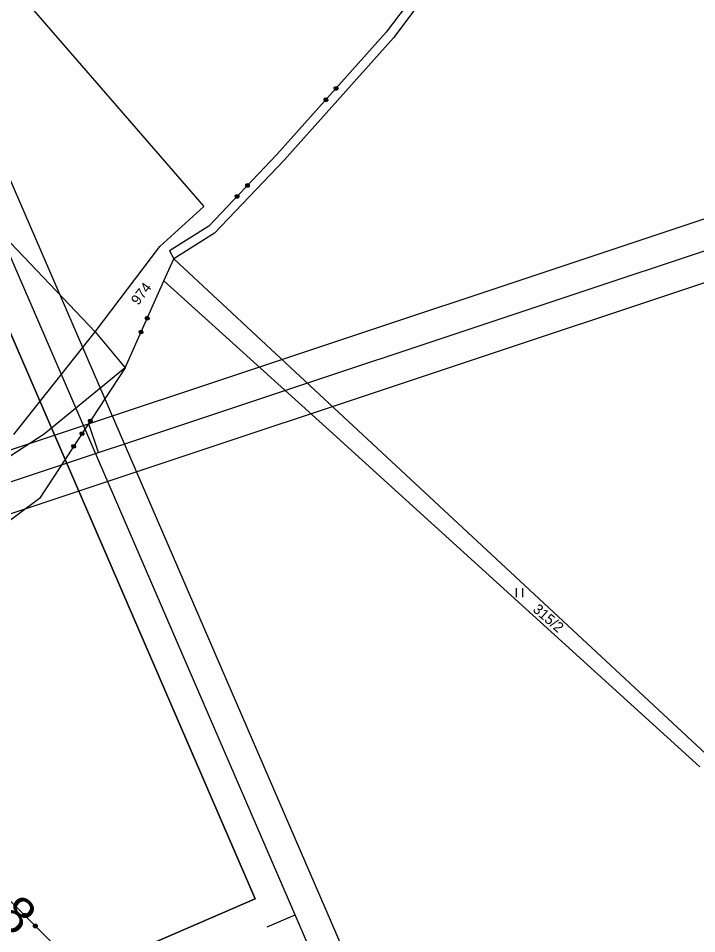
# Model space of a CAD drawing. Extents: x -866656 to -858817, y -1041816 to -1038653.
# Drawn here: x -864585 to -864473.3, y -1041373 to -1041222.2 of the extents above; entities that cross this region are included whole.
import ezdxf

# ---------------------------------------------------------------- set-up
doc = ezdxf.new("R2010")
doc.units = 0
for name, color, linetype in [('tisk ramy', 7, 'Continuous'), ('Vrstva 1', 7, 'Continuous'), ('Vrstva 3', 7, 'Continuous'), ('Vrstva 7', 7, 'Continuous')]:
    doc.layers.add(name, color=color, linetype=linetype)

msp = doc.modelspace()

# ---------------------------------------------------------------- linework, layer by layer
at = {"layer": 'tisk ramy'}
for p, q in [((-864571.85, -1041293.7), (-864573.43, -1041288.96)), ((-864544.02, -1041371.84), (-864539.44, -1041369.86))]:
    msp.add_line(p, q, dxfattribs=at)
for points in [[(-865224.28, -1040522.07), (-864724.07, -1041678.52), (-864451.49, -1041560.62), (-864951.69, -1040404.17)], [(-864954.3, -1040410.74), (-864458.06, -1041558.01), (-864721.47, -1041671.94), (-865217.7, -1040524.67)], [(-865211.14, -1040527.28), (-864800.25, -1041477.22), (-864546.01, -1041367.26), (-864956.9, -1040417.31)], [(-864956.9, -1040417.31), (-864546.01, -1041367.26), (-864800.25, -1041477.22), (-865211.14, -1040527.28)], [(-864678.84, -1041637.08), (-863881.88, -1041371.71), (-863975.7, -1041089.93), (-864772.67, -1041355.3)], [(-863888.2, -1041368.54), (-864675.68, -1041630.76), (-864766.35, -1041358.47), (-863978.87, -1041096.25)], [(-864672.52, -1041624.44), (-864089.02, -1041430.15), (-864176.53, -1041167.33), (-864760.03, -1041361.63)]]:
    msp.add_lwpolyline(points, close=True, dxfattribs=at)
at = {"layer": 'Vrstva 1'}
for p, q in [((-864624.71, -1041172.2), (-864554.46, -1041253.14)), ((-864513.59, -1041212.5), (-864523.24, -1041225.36)), ((-864523.24, -1041225.36), (-864541.25, -1041245.54)), ((-864541.25, -1041245.54), (-864552.72, -1041257.58)), ((-864561.73, -1041259.78), (-864554.46, -1041253.14)), ((-864552.72, -1041257.58), (-864559.43, -1041261.8)), ((-864572.38, -1041273.79), (-864561.73, -1041259.78)), ((-864530.65, -1041288.58), (-864559.43, -1041261.8)), ((-864561.06, -1041265.43), (-864533.75, -1041290.09)), ((-864585.8, -1041290.74), (-864572.38, -1041273.79)), ((-864567.45, -1041279.73), (-864580.81, -1041290.66)), ((-864470.92, -1041344.11), (-864530.65, -1041288.58)), ((-864580.81, -1041290.66), (-864609.48, -1041309.4)), ((-864533.75, -1041290.09), (-864472.75, -1041345.47)), ((-864502.98, -1041317.55), (-864502.98, -1041316.05)), ((-864501.98, -1041316.05), (-864501.98, -1041317.55))]:
    msp.add_line(p, q, dxfattribs=at)
at = {"layer": 'Vrstva 3'}
for p, q in [((-864514.79, -1041211.61), (-864524.44, -1041224.46)), ((-864524.44, -1041224.46), (-864542.42, -1041244.6)), ((-864524.44, -1041224.46), (-864542.42, -1041244.6)), ((-864532.99, -1041233.58), (-864532.85, -1041233.44)), ((-864532.99, -1041233.58), (-864532.85, -1041233.44)), ((-864532.97, -1041233.87), (-864532.99, -1041233.58)), ((-864532.97, -1041233.87), (-864532.99, -1041233.58)), ((-864532.82, -1041234), (-864532.97, -1041233.87)), ((-864532.82, -1041234), (-864532.97, -1041233.87)), ((-864532.91, -1041233.65), (-864532.78, -1041233.5)), ((-864532.91, -1041233.65), (-864532.78, -1041233.5)), ((-864532.61, -1041233.92), (-864532.91, -1041233.65)), ((-864532.61, -1041233.92), (-864532.91, -1041233.65)), ((-864532.91, -1041233.79), (-864532.76, -1041233.93)), ((-864532.91, -1041233.79), (-864532.76, -1041233.93)), ((-864532.85, -1041233.44), (-864532.57, -1041233.42)), ((-864532.85, -1041233.44), (-864532.57, -1041233.42)), ((-864532.85, -1041233.58), (-864532.55, -1041233.84)), ((-864532.85, -1041233.58), (-864532.55, -1041233.84)), ((-864532.54, -1041233.98), (-864532.82, -1041234)), ((-864532.54, -1041233.98), (-864532.82, -1041234)), ((-864532.78, -1041233.5), (-864532.48, -1041233.77)), ((-864532.78, -1041233.5), (-864532.48, -1041233.77)), ((-864532.76, -1041233.93), (-864532.61, -1041233.92)), ((-864532.76, -1041233.93), (-864532.61, -1041233.92)), ((-864532.49, -1041233.63), (-864532.64, -1041233.49)), ((-864532.49, -1041233.63), (-864532.64, -1041233.49)), ((-864532.57, -1041233.42), (-864532.42, -1041233.55)), ((-864532.57, -1041233.42), (-864532.42, -1041233.55)), ((-864532.41, -1041233.83), (-864532.54, -1041233.98)), ((-864532.41, -1041233.83), (-864532.54, -1041233.98)), ((-864532.48, -1041233.77), (-864532.49, -1041233.63)), ((-864532.48, -1041233.77), (-864532.49, -1041233.63)), ((-864532.42, -1041233.55), (-864532.41, -1041233.83)), ((-864532.42, -1041233.55), (-864532.41, -1041233.83)), ((-864534.65, -1041235.45), (-864534.52, -1041235.3)), ((-864534.65, -1041235.45), (-864534.52, -1041235.3)), ((-864534.64, -1041235.73), (-864534.65, -1041235.45)), ((-864534.64, -1041235.73), (-864534.65, -1041235.45)), ((-864534.49, -1041235.86), (-864534.64, -1041235.73)), ((-864534.49, -1041235.86), (-864534.64, -1041235.73)), ((-864534.58, -1041235.52), (-864534.44, -1041235.37)), ((-864534.58, -1041235.52), (-864534.44, -1041235.37)), ((-864534.28, -1041235.78), (-864534.58, -1041235.52)), ((-864534.28, -1041235.78), (-864534.58, -1041235.52)), ((-864534.57, -1041235.66), (-864534.42, -1041235.79)), ((-864534.57, -1041235.66), (-864534.42, -1041235.79)), ((-864534.52, -1041235.3), (-864534.24, -1041235.28)), ((-864534.52, -1041235.3), (-864534.24, -1041235.28)), ((-864534.51, -1041235.44), (-864534.21, -1041235.71)), ((-864534.51, -1041235.44), (-864534.21, -1041235.71)), ((-864534.21, -1041235.85), (-864534.49, -1041235.86)), ((-864534.21, -1041235.85), (-864534.49, -1041235.86)), ((-864534.44, -1041235.37), (-864534.15, -1041235.63)), ((-864534.44, -1041235.37), (-864534.15, -1041235.63)), ((-864534.42, -1041235.79), (-864534.28, -1041235.78)), ((-864534.42, -1041235.79), (-864534.28, -1041235.78)), ((-864534.15, -1041235.49), (-864534.3, -1041235.36)), ((-864534.15, -1041235.49), (-864534.3, -1041235.36)), ((-864534.24, -1041235.28), (-864534.09, -1041235.42)), ((-864534.24, -1041235.28), (-864534.09, -1041235.42)), ((-864534.07, -1041235.7), (-864534.21, -1041235.85)), ((-864534.07, -1041235.7), (-864534.21, -1041235.85)), ((-864534.15, -1041235.63), (-864534.15, -1041235.49)), ((-864534.15, -1041235.63), (-864534.15, -1041235.49)), ((-864534.09, -1041235.42), (-864534.07, -1041235.7)), ((-864534.09, -1041235.42), (-864534.07, -1041235.7)), ((-864604.47, -1041240.2), (-864572.38, -1041273.79)), ((-864604.47, -1041240.2), (-864572.38, -1041273.79)), ((-864542.42, -1041244.6), (-864553.66, -1041256.41)), ((-864542.42, -1041244.6), (-864553.66, -1041256.41)), ((-864547.57, -1041249.57), (-864547.43, -1041249.43)), ((-864547.57, -1041249.57), (-864547.43, -1041249.43)), ((-864547.56, -1041249.86), (-864547.57, -1041249.57)), ((-864547.56, -1041249.86), (-864547.57, -1041249.57)), ((-864547.42, -1041249.99), (-864547.56, -1041249.86)), ((-864547.42, -1041249.99), (-864547.56, -1041249.86)), ((-864547.49, -1041249.64), (-864547.36, -1041249.5)), ((-864547.49, -1041249.64), (-864547.36, -1041249.5)), ((-864547.21, -1041249.92), (-864547.49, -1041249.64)), ((-864547.21, -1041249.92), (-864547.49, -1041249.64)), ((-864547.49, -1041249.78), (-864547.35, -1041249.92)), ((-864547.49, -1041249.78), (-864547.35, -1041249.92)), ((-864547.43, -1041249.43), (-864547.15, -1041249.42)), ((-864547.43, -1041249.43), (-864547.15, -1041249.42)), ((-864547.43, -1041249.57), (-864547.14, -1041249.85)), ((-864547.43, -1041249.57), (-864547.14, -1041249.85)), ((-864547.13, -1041249.99), (-864547.42, -1041249.99)), ((-864547.13, -1041249.99), (-864547.42, -1041249.99)), ((-864547.36, -1041249.5), (-864547.07, -1041249.77)), ((-864547.36, -1041249.5), (-864547.07, -1041249.77)), ((-864547.35, -1041249.92), (-864547.21, -1041249.92)), ((-864547.35, -1041249.92), (-864547.21, -1041249.92)), ((-864547.07, -1041249.63), (-864547.22, -1041249.49)), ((-864547.07, -1041249.63), (-864547.22, -1041249.49)), ((-864547.15, -1041249.42), (-864547, -1041249.56)), ((-864547.15, -1041249.42), (-864547, -1041249.56)), ((-864546.99, -1041249.84), (-864547.13, -1041249.99)), ((-864546.99, -1041249.84), (-864547.13, -1041249.99)), ((-864547.07, -1041249.77), (-864547.07, -1041249.63)), ((-864547.07, -1041249.77), (-864547.07, -1041249.63)), ((-864547, -1041249.56), (-864546.99, -1041249.84)), ((-864547, -1041249.56), (-864546.99, -1041249.84)), ((-864549.29, -1041251.38), (-864549.15, -1041251.24)), ((-864549.29, -1041251.38), (-864549.15, -1041251.24)), ((-864549.28, -1041251.67), (-864549.29, -1041251.38)), ((-864549.28, -1041251.67), (-864549.29, -1041251.38)), ((-864549.22, -1041251.45), (-864549.08, -1041251.31)), ((-864549.22, -1041251.45), (-864549.08, -1041251.31)), ((-864548.93, -1041251.73), (-864549.22, -1041251.45)), ((-864548.93, -1041251.73), (-864549.22, -1041251.45)), ((-864549.15, -1041251.24), (-864548.87, -1041251.23)), ((-864549.15, -1041251.24), (-864548.87, -1041251.23)), ((-864549.15, -1041251.38), (-864548.86, -1041251.66)), ((-864549.15, -1041251.38), (-864548.86, -1041251.66)), ((-864549.08, -1041251.31), (-864548.79, -1041251.58)), ((-864549.08, -1041251.31), (-864548.79, -1041251.58)), ((-864548.79, -1041251.44), (-864548.94, -1041251.31)), ((-864548.79, -1041251.44), (-864548.94, -1041251.31)), ((-864548.87, -1041251.23), (-864548.72, -1041251.37)), ((-864548.87, -1041251.23), (-864548.72, -1041251.37)), ((-864548.79, -1041251.58), (-864548.79, -1041251.44)), ((-864548.79, -1041251.58), (-864548.79, -1041251.44)), ((-864548.72, -1041251.37), (-864548.72, -1041251.65)), ((-864548.72, -1041251.37), (-864548.72, -1041251.65)), ((-864549.14, -1041251.81), (-864549.28, -1041251.67)), ((-864549.14, -1041251.81), (-864549.28, -1041251.67)), ((-864549.21, -1041251.59), (-864549.07, -1041251.73)), ((-864549.21, -1041251.59), (-864549.07, -1041251.73)), ((-864548.86, -1041251.8), (-864549.14, -1041251.81)), ((-864548.86, -1041251.8), (-864549.14, -1041251.81)), ((-864549.07, -1041251.73), (-864548.93, -1041251.73)), ((-864549.07, -1041251.73), (-864548.93, -1041251.73)), ((-864548.72, -1041251.65), (-864548.86, -1041251.8)), ((-864548.72, -1041251.65), (-864548.86, -1041251.8)), ((-864553.66, -1041256.41), (-864560.14, -1041260.47)), ((-864553.66, -1041256.41), (-864560.14, -1041260.47)), ((-864560.14, -1041260.47), (-864559.43, -1041261.8)), ((-864560.14, -1041260.47), (-864559.43, -1041261.8)), ((-864561.06, -1041265.43), (-864559.43, -1041261.8)), ((-864561.06, -1041265.43), (-864559.43, -1041261.8)), ((-864567.45, -1041279.73), (-864561.06, -1041265.43)), ((-864567.45, -1041279.73), (-864561.06, -1041265.43)), ((-864564.12, -1041271.54), (-864564.04, -1041271.36)), ((-864564.12, -1041271.54), (-864564.04, -1041271.36)), ((-864564.02, -1041271.81), (-864564.12, -1041271.54)), ((-864564.02, -1041271.81), (-864564.12, -1041271.54)), ((-864564.04, -1041271.36), (-864563.78, -1041271.26)), ((-864564.04, -1041271.36), (-864563.78, -1041271.26)), ((-864564.03, -1041271.59), (-864563.95, -1041271.4)), ((-864564.03, -1041271.59), (-864563.95, -1041271.4)), ((-864563.66, -1041271.75), (-864564.03, -1041271.59)), ((-864563.66, -1041271.75), (-864564.03, -1041271.59)), ((-864563.84, -1041271.89), (-864564.02, -1041271.81)), ((-864563.84, -1041271.89), (-864564.02, -1041271.81)), ((-864563.99, -1041271.49), (-864563.62, -1041271.66)), ((-864563.99, -1041271.49), (-864563.62, -1041271.66)), ((-864563.98, -1041271.72), (-864563.8, -1041271.8)), ((-864563.98, -1041271.72), (-864563.8, -1041271.8)), ((-864563.95, -1041271.4), (-864563.58, -1041271.57)), ((-864563.95, -1041271.4), (-864563.58, -1041271.57)), ((-864563.57, -1041271.79), (-864563.84, -1041271.89)), ((-864563.57, -1041271.79), (-864563.84, -1041271.89)), ((-864563.63, -1041271.43), (-864563.82, -1041271.35)), ((-864563.63, -1041271.43), (-864563.82, -1041271.35)), ((-864563.8, -1041271.8), (-864563.66, -1041271.75)), ((-864563.8, -1041271.8), (-864563.66, -1041271.75)), ((-864563.78, -1041271.26), (-864563.59, -1041271.34)), ((-864563.78, -1041271.26), (-864563.59, -1041271.34)), ((-864563.58, -1041271.57), (-864563.63, -1041271.43)), ((-864563.58, -1041271.57), (-864563.63, -1041271.43)), ((-864563.59, -1041271.34), (-864563.49, -1041271.61)), ((-864563.59, -1041271.34), (-864563.49, -1041271.61)), ((-864563.49, -1041271.61), (-864563.57, -1041271.79)), ((-864563.49, -1041271.61), (-864563.57, -1041271.79)), ((-864572.38, -1041273.79), (-864567.45, -1041279.73)), ((-864572.38, -1041273.79), (-864567.45, -1041279.73)), ((-864565.14, -1041273.83), (-864565.06, -1041273.64)), ((-864565.14, -1041273.83), (-864565.06, -1041273.64)), ((-864565.04, -1041274.09), (-864565.14, -1041273.83)), ((-864565.04, -1041274.09), (-864565.14, -1041273.83)), ((-864565.06, -1041273.64), (-864564.8, -1041273.54)), ((-864565.06, -1041273.64), (-864564.8, -1041273.54)), ((-864565.05, -1041273.87), (-864564.97, -1041273.69)), ((-864565.05, -1041273.87), (-864564.97, -1041273.69)), ((-864564.68, -1041274.03), (-864565.05, -1041273.87)), ((-864564.68, -1041274.03), (-864565.05, -1041273.87)), ((-864564.86, -1041274.17), (-864565.04, -1041274.09)), ((-864564.86, -1041274.17), (-864565.04, -1041274.09)), ((-864565.01, -1041273.78), (-864564.64, -1041273.94)), ((-864565.01, -1041273.78), (-864564.64, -1041273.94)), ((-864565, -1041274), (-864564.82, -1041274.08)), ((-864565, -1041274), (-864564.82, -1041274.08)), ((-864564.97, -1041273.69), (-864564.6, -1041273.85)), ((-864564.97, -1041273.69), (-864564.6, -1041273.85)), ((-864564.59, -1041274.07), (-864564.86, -1041274.17)), ((-864564.59, -1041274.07), (-864564.86, -1041274.17)), ((-864564.65, -1041273.72), (-864564.83, -1041273.63)), ((-864564.65, -1041273.72), (-864564.83, -1041273.63)), ((-864564.82, -1041274.08), (-864564.68, -1041274.03)), ((-864564.82, -1041274.08), (-864564.68, -1041274.03)), ((-864564.8, -1041273.54), (-864564.61, -1041273.62)), ((-864564.8, -1041273.54), (-864564.61, -1041273.62)), ((-864564.6, -1041273.85), (-864564.65, -1041273.72)), ((-864564.6, -1041273.85), (-864564.65, -1041273.72)), ((-864564.61, -1041273.62), (-864564.51, -1041273.89)), ((-864564.61, -1041273.62), (-864564.51, -1041273.89)), ((-864564.51, -1041273.89), (-864564.59, -1041274.07)), ((-864564.51, -1041273.89), (-864564.59, -1041274.07)), ((-864567.45, -1041279.73), (-864581.55, -1041301.3)), ((-864567.45, -1041279.73), (-864581.55, -1041301.3)), ((-864573.49, -1041288.43), (-864573.38, -1041288.26)), ((-864573.49, -1041288.43), (-864573.38, -1041288.26)), ((-864573.43, -1041288.7), (-864573.49, -1041288.43)), ((-864573.43, -1041288.7), (-864573.49, -1041288.43)), ((-864573.27, -1041288.81), (-864573.43, -1041288.7)), ((-864573.27, -1041288.81), (-864573.43, -1041288.7)), ((-864573.41, -1041288.48), (-864573.3, -1041288.31)), ((-864573.41, -1041288.48), (-864573.3, -1041288.31)), ((-864573.07, -1041288.7), (-864573.41, -1041288.48)), ((-864573.07, -1041288.7), (-864573.41, -1041288.48)), ((-864573.38, -1041288.26), (-864573.11, -1041288.2)), ((-864573.38, -1041288.26), (-864573.11, -1041288.2)), ((-864573.38, -1041288.62), (-864573.21, -1041288.73)), ((-864573.38, -1041288.62), (-864573.21, -1041288.73)), ((-864573.35, -1041288.4), (-864573.02, -1041288.61)), ((-864573.35, -1041288.4), (-864573.02, -1041288.61)), ((-864573.3, -1041288.31), (-864572.96, -1041288.53)), ((-864573.3, -1041288.31), (-864572.96, -1041288.53)), ((-864572.99, -1041288.75), (-864573.27, -1041288.81)), ((-864572.99, -1041288.75), (-864573.27, -1041288.81)), ((-864573.21, -1041288.73), (-864573.07, -1041288.7)), ((-864573.21, -1041288.73), (-864573.07, -1041288.7)), ((-864572.99, -1041288.39), (-864573.16, -1041288.28)), ((-864572.99, -1041288.39), (-864573.16, -1041288.28)), ((-864573.11, -1041288.2), (-864572.94, -1041288.31)), ((-864573.11, -1041288.2), (-864572.94, -1041288.31)), ((-864572.96, -1041288.53), (-864572.99, -1041288.39)), ((-864572.96, -1041288.53), (-864572.99, -1041288.39)), ((-864572.88, -1041288.59), (-864572.99, -1041288.75)), ((-864572.88, -1041288.59), (-864572.99, -1041288.75)), ((-864572.94, -1041288.31), (-864572.88, -1041288.59)), ((-864572.94, -1041288.31), (-864572.88, -1041288.59)), ((-864574.86, -1041290.52), (-864574.75, -1041290.35)), ((-864574.86, -1041290.52), (-864574.75, -1041290.35)), ((-864574.8, -1041290.8), (-864574.86, -1041290.52)), ((-864574.8, -1041290.8), (-864574.86, -1041290.52)), ((-864574.78, -1041290.57), (-864574.67, -1041290.41)), ((-864574.78, -1041290.57), (-864574.67, -1041290.41)), ((-864574.44, -1041290.79), (-864574.78, -1041290.57)), ((-864574.44, -1041290.79), (-864574.78, -1041290.57)), ((-864574.75, -1041290.35), (-864574.47, -1041290.29)), ((-864574.75, -1041290.35), (-864574.47, -1041290.29)), ((-864574.72, -1041290.49), (-864574.39, -1041290.71)), ((-864574.72, -1041290.49), (-864574.39, -1041290.71)), ((-864574.67, -1041290.41), (-864574.33, -1041290.62)), ((-864574.67, -1041290.41), (-864574.33, -1041290.62)), ((-864574.36, -1041290.49), (-864574.53, -1041290.38)), ((-864574.36, -1041290.49), (-864574.53, -1041290.38)), ((-864574.47, -1041290.29), (-864574.31, -1041290.4)), ((-864574.47, -1041290.29), (-864574.31, -1041290.4)), ((-864574.33, -1041290.62), (-864574.36, -1041290.49)), ((-864574.33, -1041290.62), (-864574.36, -1041290.49)), ((-864574.25, -1041290.68), (-864574.36, -1041290.85)), ((-864574.25, -1041290.68), (-864574.36, -1041290.85)), ((-864574.31, -1041290.4), (-864574.25, -1041290.68)), ((-864574.31, -1041290.4), (-864574.25, -1041290.68)), ((-864574.64, -1041290.9), (-864574.8, -1041290.8)), ((-864574.64, -1041290.9), (-864574.8, -1041290.8)), ((-864574.75, -1041290.71), (-864574.58, -1041290.82)), ((-864574.75, -1041290.71), (-864574.58, -1041290.82)), ((-864574.36, -1041290.85), (-864574.64, -1041290.9)), ((-864574.36, -1041290.85), (-864574.64, -1041290.9)), ((-864574.58, -1041290.82), (-864574.44, -1041290.79)), ((-864574.58, -1041290.82), (-864574.44, -1041290.79)), ((-864576.23, -1041292.61), (-864576.12, -1041292.44)), ((-864576.23, -1041292.61), (-864576.12, -1041292.44)), ((-864576.17, -1041292.89), (-864576.23, -1041292.61)), ((-864576.17, -1041292.89), (-864576.23, -1041292.61)), ((-864576, -1041293), (-864576.17, -1041292.89)), ((-864576, -1041293), (-864576.17, -1041292.89)), ((-864576.14, -1041292.67), (-864576.04, -1041292.5)), ((-864576.14, -1041292.67), (-864576.04, -1041292.5)), ((-864575.81, -1041292.88), (-864576.14, -1041292.67)), ((-864575.81, -1041292.88), (-864576.14, -1041292.67)), ((-864576.12, -1041292.44), (-864575.84, -1041292.39)), ((-864576.12, -1041292.44), (-864575.84, -1041292.39)), ((-864576.11, -1041292.8), (-864575.95, -1041292.91)), ((-864576.11, -1041292.8), (-864575.95, -1041292.91)), ((-864576.09, -1041292.58), (-864575.76, -1041292.8)), ((-864576.09, -1041292.58), (-864575.76, -1041292.8)), ((-864576.04, -1041292.5), (-864575.7, -1041292.72)), ((-864576.04, -1041292.5), (-864575.7, -1041292.72)), ((-864575.73, -1041292.94), (-864576, -1041293)), ((-864575.73, -1041292.94), (-864576, -1041293)), ((-864575.95, -1041292.91), (-864575.81, -1041292.88)), ((-864575.95, -1041292.91), (-864575.81, -1041292.88)), ((-864575.73, -1041292.58), (-864575.9, -1041292.47)), ((-864575.73, -1041292.58), (-864575.9, -1041292.47)), ((-864575.84, -1041292.39), (-864575.67, -1041292.49)), ((-864575.84, -1041292.39), (-864575.67, -1041292.49)), ((-864575.7, -1041292.72), (-864575.73, -1041292.58)), ((-864575.7, -1041292.72), (-864575.73, -1041292.58)), ((-864575.62, -1041292.77), (-864575.73, -1041292.94)), ((-864575.62, -1041292.77), (-864575.73, -1041292.94)), ((-864575.67, -1041292.49), (-864575.62, -1041292.77)), ((-864575.67, -1041292.49), (-864575.62, -1041292.77)), ((-864581.55, -1041301.3), (-864601.98, -1041316.45)), ((-864581.55, -1041301.3), (-864601.98, -1041316.45)), ((-864574.94, -1041378.96), (-864589.39, -1041364.59)), ((-864574.94, -1041378.96), (-864589.39, -1041364.59)), ((-864584.29, -1041369.8), (-864584.15, -1041369.66)), ((-864584.29, -1041369.8), (-864584.15, -1041369.66)), ((-864584.29, -1041370.08), (-864584.29, -1041369.8)), ((-864584.29, -1041370.08), (-864584.29, -1041369.8)), ((-864584.15, -1041370.22), (-864584.29, -1041370.08)), ((-864584.15, -1041370.22), (-864584.29, -1041370.08)), ((-864584.08, -1041369.73), (-864584.22, -1041369.87)), ((-864584.22, -1041370.01), (-864583.94, -1041369.73)), ((-864584.08, -1041369.73), (-864584.22, -1041369.87)), ((-864584.22, -1041370.01), (-864583.94, -1041369.73)), ((-864584.22, -1041369.87), (-864584.22, -1041370.01)), ((-864584.22, -1041369.87), (-864584.22, -1041370.01)), ((-864584.15, -1041369.66), (-864583.87, -1041369.66)), ((-864584.15, -1041369.66), (-864583.87, -1041369.66)), ((-864583.87, -1041369.8), (-864584.15, -1041370.08)), ((-864583.87, -1041369.8), (-864584.15, -1041370.08)), ((-864583.87, -1041370.22), (-864584.15, -1041370.22)), ((-864583.87, -1041370.22), (-864584.15, -1041370.22)), ((-864583.8, -1041369.87), (-864584.08, -1041370.15)), ((-864583.8, -1041369.87), (-864584.08, -1041370.15)), ((-864584.08, -1041370.15), (-864583.94, -1041370.15)), ((-864584.08, -1041370.15), (-864583.94, -1041370.15)), ((-864583.94, -1041369.73), (-864583.8, -1041369.87)), ((-864583.94, -1041369.73), (-864583.8, -1041369.87)), ((-864583.94, -1041370.15), (-864583.8, -1041370.01)), ((-864583.94, -1041370.15), (-864583.8, -1041370.01)), ((-864583.87, -1041369.66), (-864583.73, -1041369.8)), ((-864583.87, -1041369.66), (-864583.73, -1041369.8)), ((-864583.72, -1041370.08), (-864583.87, -1041370.22)), ((-864583.72, -1041370.08), (-864583.87, -1041370.22)), ((-864583.73, -1041369.8), (-864583.72, -1041370.08)), ((-864583.73, -1041369.8), (-864583.72, -1041370.08)), ((-864582.52, -1041371.56), (-864582.38, -1041371.42)), ((-864582.52, -1041371.56), (-864582.38, -1041371.42)), ((-864582.52, -1041371.85), (-864582.52, -1041371.56)), ((-864582.52, -1041371.85), (-864582.52, -1041371.56)), ((-864582.38, -1041371.99), (-864582.52, -1041371.85)), ((-864582.38, -1041371.99), (-864582.52, -1041371.85)), ((-864582.31, -1041371.49), (-864582.45, -1041371.63)), ((-864582.45, -1041371.78), (-864582.17, -1041371.49)), ((-864582.31, -1041371.49), (-864582.45, -1041371.63)), ((-864582.45, -1041371.78), (-864582.17, -1041371.49)), ((-864582.45, -1041371.63), (-864582.45, -1041371.78)), ((-864582.45, -1041371.63), (-864582.45, -1041371.78)), ((-864582.38, -1041371.42), (-864582.09, -1041371.42)), ((-864582.38, -1041371.42), (-864582.09, -1041371.42)), ((-864582.09, -1041371.56), (-864582.38, -1041371.85)), ((-864582.09, -1041371.56), (-864582.38, -1041371.85)), ((-864582.09, -1041371.99), (-864582.38, -1041371.99)), ((-864582.09, -1041371.99), (-864582.38, -1041371.99)), ((-864582.02, -1041371.63), (-864582.31, -1041371.92)), ((-864582.02, -1041371.63), (-864582.31, -1041371.92)), ((-864582.31, -1041371.92), (-864582.16, -1041371.92)), ((-864582.31, -1041371.92), (-864582.16, -1041371.92)), ((-864582.17, -1041371.49), (-864582.02, -1041371.63)), ((-864582.17, -1041371.49), (-864582.02, -1041371.63)), ((-864582.16, -1041371.92), (-864582.02, -1041371.77)), ((-864582.16, -1041371.92), (-864582.02, -1041371.77)), ((-864582.09, -1041371.42), (-864581.95, -1041371.56)), ((-864582.09, -1041371.42), (-864581.95, -1041371.56)), ((-864581.95, -1041371.84), (-864582.09, -1041371.99)), ((-864581.95, -1041371.84), (-864582.09, -1041371.99)), ((-864581.95, -1041371.56), (-864581.95, -1041371.84)), ((-864581.95, -1041371.56), (-864581.95, -1041371.84))]:
    msp.add_line(p, q, dxfattribs=at)

# ---------------------------------------------------------------- texts
at = {"layer": 'Vrstva 1'}
for s, rotation, p in [('974', 52.7798, (-864565.28, -1041269.54)), ('315/2', 319.0535, (-864500.4, -1041319.76))]:
    msp.add_text(s, height=1.7, rotation=rotation, dxfattribs=at).set_placement(p)
at = {"layer": 'Vrstva 7'}
msp.add_text('5,8', height=6, rotation=318.1506, dxfattribs=at).set_placement((-864593.85, -1041366.15))

doc.saveas('drawing.dxf')
